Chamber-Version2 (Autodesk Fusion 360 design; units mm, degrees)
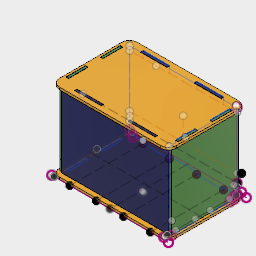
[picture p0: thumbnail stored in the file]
parameter "height" = 30
parameter "gap" = 0.2
parameter "tabWidth" = 30
parameter "tabGap" = 0.1
parameter "thickness" = 3
parameter "offset" = 4
parameter "width" = 150
parameter "length" = 100
parameter "fillet" = 10
sketch "Sketch2" plane through (0, 0, 0) normal (0, 1, 0) x axis (1, 0, 0)
  line L1 (150, 0) -> (0, 0)
  line L2 (150, 100) -> (150, 0)
  line L3 (0, 100) -> (150, 100)
  line L4 (0, 0) -> (0, 100)
  point P2 (0, 0)
  point P3 (150, 0)
  point P5 (0, 100)
  dimension "d10" distance P2 P3 = 150 (= "width")
  dimension "d11" distance P2 P5 = 100 (= "length")
extrude "Extrude1" new body sketch "Sketch2" along normal blind 3 (= "thickness") bodies "Bottom"
fillet "Fillet1" radius 10 (= "fillet")
work_plane "WorkPlane1" sketch "Sketch2" AlongDistance 30 (= "height")
fillet "Fillet2" radius 10 (= "fillet")
fillet "Fillet3" radius 10 (= "fillet")
fillet "Fillet4" radius 10 (= "fillet")
sketch "BOTTOM PartA" plane through (40, 30, -60) normal (0, 1, 0) x axis (1, 0, 0)
  line L1 (-30, 40) -> (100, 40)
  line L2 (-40, -50) -> (-40, 30)
  line L3 (100, -60) -> (-30, -60)
  line L4 (110, 30) -> (110, -50)
  arc A1 centre (100, 30) radius 10 clockwise from (100, 40) to (110, 30)
  arc A2 centre (-30, 30) radius 10 clockwise from (-40, 30) to (-30, 40)
  arc A3 centre (-30, -50) radius 10 clockwise from (-30, -60) to (-40, -50)
  arc A4 centre (100, -50) radius 10 clockwise from (110, -50) to (100, -60)
work_plane "WorkPlane2" AlongDistance -6 (= "-thickness * 2")
sketch "RIGHT" plane through (144, 1, -60) normal (1, 0, 0) x axis (0, 0, -1)
  line L1 (-50, 2.2) -> (30, 2.2)
  line L2 (-50, 2) -> (-50, -1)
  line L3 (30, -1) -> (30, 2)
  line L4 (-50, 2) -> (-60, 2)
  line L5 (-55.3241, 2.2) -> (-55.3241, 2)
  line L6 (-58.1845, 2.2) -> (-55.3241, 2.2)
  line L7 (-19.685, 102.4) -> (-44.685, 102.4)
  line L8 (-19.685, 99.2) -> (-19.685, 102.4)
  line L9 (-44.685, 102.4) -> (-44.685, 99.2)
  line L10 (-32.185, 102.4) -> (-32.185, 99.2)
  line L11 (24.7595, 102.4) -> (24.7595, 99.2)
  line L12 (-0.2405, 102.4) -> (24.7595, 102.4)
  line L13 (-0.2405, 99.2) -> (-0.2405, 102.4)
  line L14 (-44.7222, -1) -> (-44.7222, 2.2)
  line L15 (-19.7222, -1) -> (-44.7222, -1)
  line L16 (-19.7222, 2.2) -> (-19.7222, -1)
  line L17 (-0.2778, 2.2) -> (-0.2778, -1)
  line L18 (-0.2778, -1) -> (24.7222, -1)
  line L19 (24.7222, -1) -> (24.7222, 2.2)
  line L20 (-53, 15.5) -> (-50, 15.5)
  line L21 (33.0372, 15.5) -> (30.0372, 15.5)
  line L22 (-50, 2.2) -> (-55.3241, 2.2)
  line L23 (-53, 2.2) -> (-53, 15.5)
  line L24 (-53, 2.2) -> (-50, 2.2)
  line L25 (-53.036, 99.2) -> (-53, 15.5)
  line L26 (-53.036, 99.2) -> (-49.9628, 99.2)
  line L27 (33.0372, 101.1482) -> (33.0372, 15.5)
  line L28 (40, 2) -> (30, 2)
  line L29 (33.0372, 2) -> (33.0372, 101.1482)
  line L30 (33.0372, 2.2) -> (30, 2.2)
  line L31 (33.0372, 99.2027) -> (30.0372, 99.2)
  line L32 (33.0372, 2.2) -> (33.0372, 99.2027)
  line L33 (33.0372, 102) -> (33.0372, 2)
  line L34 (-53, 99.2) -> (-53, 2.2)
  line L35 (-44.685, 99.2) -> (-49.9628, 99.2)
  line L36 (-0.2405, 99.2) -> (-19.685, 99.2)
  line L37 (30.0372, 99.2) -> (24.7595, 99.2)
  point P11 (-55.3241, 2)
  point P12 (-55.3241, 2.2)
  point P16 (-44.685, 102.4)
  point P17 (-19.685, 102.4)
  point P19 (-44.685, 99.2)
  point P14 (-50, 15.5)
  point P34 (-53, 15.5)
  point P15 (30.0372, 15.5)
  point P35 (33.0372, 15.5)
  point P41 (33.0372, 2)
  point P44 (33.0372, 102)
  point P36 (-53, 2.2)
  point P45 (-53, 99.2)
  dimension "d28" distance P11 P12 = 0.2 (= "gap")
  dimension "d31" distance P16 P17 = 25 (= "length / 4")
  dimension "d32" distance P16 P19 = 3.2 (= "thickness + gap")
  dimension "d89" distance P14 P34 = 3 (= "thickness")
  dimension "d90" distance P15 P35 = 3 (= "thickness")
  dimension "d101" distance P41 P44 = 100
  dimension "d102" distance P36 P45 = 97 (= "100 mm - thickness")
extrude "Extrude3" new body sketch "RIGHT" profile of L1 L7 L8 L9 L11 L12 L13 L14 L15 L16 L17 L18 L19 along normal blind 3 (= "thickness") bodies "Right"
work_plane "WorkPlane3"
work_plane "WorkPlane4" AlongDistance -6 (= "-thickness * 2")
sketch "BACK" plane through (40, 1, -94) normal (0, 0, -1) x axis (1, 0, 0)
  line L1 (-30, 1) -> (-30, -2)
  line L2 (110, -28.8) -> (110, -29)
  line L3 (104, -15.5) -> (-94.0061, -15.5)
  line L4 (104, -26.3027) -> (-34, -26.3027)
  line L5 (35, -55.5802) -> (35, -26.3027)
  line L6 (-33.7633, -93.8824) -> (0.2632, -93.8824)
  line L7 (-16.7501, -99.1805) -> (-16.7501, -93.8824)
  line L8 (-16.7501, -102.3805) -> (-16.7501, -99.1805)
  line L9 (35, -93.8824) -> (-0.5953, -93.8824)
  line L10 (17.2024, -99.1805) -> (17.2024, -93.8824)
  line L11 (17.2024, -102.3805) -> (17.2024, -99.1805)
  line L12 (17.2024, -102.3805) -> (-16.7501, -102.3805)
  line L13 (-16.7501, 1) -> (-16.7501, -2.2)
  line L14 (17.2024, 1) -> (17.2024, -2.2)
  line L15 (17.2024, 1) -> (-16.7501, 1)
  line L16 (69.5, -93.8747) -> (35, -93.8824)
  line L17 (104, -93.8747) -> (69.5, -93.8747)
  line L18 (52.25, -99.1805) -> (52.25, -93.8786)
  line L19 (86.75, -99.1805) -> (86.75, -93.8747)
  line L20 (52.25, 1) -> (52.25, -2.2)
  line L21 (86.75, 1) -> (86.75, -2.2)
  line L22 (86.75, 1) -> (52.25, 1)
  line L23 (52.25, -102.3805) -> (52.25, -99.1805)
  line L24 (86.75, -102.3805) -> (86.75, -99.1805)
  line L25 (86.75, -102.3805) -> (52.25, -102.3805)
  line L26 (17.2024, -99.1805) -> (52.25, -99.1805)
  line L27 (52.25, -2.2) -> (17.2024, -2.2)
  line L28 (103.8, -2.2) -> (103.8, -10.9343)
  line L29 (103.8, -93.8747) -> (103.8, -10.9343)
  line L30 (103.8, -99.1805) -> (86.75, -99.1805)
  line L31 (103.8, -93.8747) -> (103.8, -99.1805)
  line L32 (103.8, -2.2) -> (86.75, -2.2)
  line L33 (104, -2.2) -> (104, -99.2027)
  line L34 (104, -2.2) -> (104, -15.5)
  line L35 (103.9, -10.9313) -> (104, -10.9313)
  line L36 (-33.7001, -20.8392) -> (-33.6001, -20.8392)
  line L37 (-33.7001, -99.1805) -> (-33.7001, -20.8392)
  line L38 (-33.7001, -99.1805) -> (-16.7501, -99.1805)
  line L39 (-33.7001, -15.5) -> (-33.7001, -20.8392)
  line L40 (-33.7001, -2.1805) -> (-33.7001, -15.5)
  line L41 (-33.7001, -99.1805) -> (-33.7001, -2.1805)
  line L42 (-16.75, -2.1805) -> (-33.7001, -2.1805)
  point P17 (-16.7501, -99.1805)
  point P18 (-16.7501, -102.3805)
  point P22 (17.2024, -99.1805)
  point P23 (17.2024, -102.3805)
  point P24 (-16.7501, -2.2)
  point P25 (-16.7501, 1)
  point P26 (17.2024, -2.2)
  point P27 (17.2024, 1)
  point P34 (52.25, -2.2)
  point P35 (52.25, 1)
  point P36 (86.75, -2.2)
  point P37 (86.75, 1)
  point P31 (52.25, -99.1805)
  point P38 (52.25, -102.3805)
  point P33 (86.75, -99.1805)
  point P39 (86.75, -102.3805)
  point P49 (104, -10.9313)
  point P50 (103.9, -10.9313)
  point P51 (-33.6001, -20.8392)
  point P52 (-33.7001, -20.8392)
  point P55 (-33.7001, -2.1805)
  point P56 (-33.7001, -99.1805)
  dimension "d53" distance P17 P18 = 3.2 (= "thickness + gap")
  dimension "d54" distance P22 P23 = 3.2 (= "thickness + gap")
  dimension "d55" distance P24 P25 = 3.2 (= "thickness + gap")
  dimension "d56" distance P26 P27 = 3.2 (= "thickness + gap")
  dimension "d57" distance P34 P35 = 3.2 (= "thickness + gap")
  dimension "d58" distance P36 P37 = 3.2 (= "thickness + gap")
  dimension "d59" distance P31 P38 = 3.2 (= "thickness + gap")
  dimension "d60" distance P33 P39 = 3.2 (= "thickness + gap")
  dimension "d97" distance P49 P50 = 0.1
  dimension "d98" distance P51 P52 = 0.1
  dimension "d103" distance P55 P56 = 97 (= "100 mm - thickness")
work_plane "WorkPlane5"
sketch "BOTTOM PartB" plane through (0, 0, 0) normal (0, -1, 0) x axis (1, 0, 0)
  line L1 (150, -10) -> (150, -90)
  line L2 (10, 0) -> (140, 0)
  line L3 (0, -90) -> (0, -10)
  line L4 (140, -100) -> (10, -100)
  line L5 (150, -50) -> (0, -50)
  line L6 (75, 0) -> (75, -100)
  line L7 (76, -40.2778) -> (78, -40.2778)
  line L8 (23.2499, 0) -> (23.2499, -94)
  line L9 (57.2024, 0) -> (57.2024, -94)
  line L10 (92.25, 0) -> (92.25, -94)
  line L11 (126.75, 0) -> (126.75, -94)
  line L12 (143.85, -84.7722) -> (146.95, -84.7722)
  line L13 (143.85, -59.6722) -> (143.85, -84.7722)
  line L14 (146.95, -59.6722) -> (143.85, -59.6722)
  line L15 (146.95, -84.7722) -> (146.95, -59.6722)
  line L16 (147.05, -15.2278) -> (143.95, -15.2278)
  line L17 (143.95, -15.2278) -> (143.95, -40.3278)
  line L18 (147.05, -40.3278) -> (147.05, -15.2278)
  line L19 (143.95, -40.3278) -> (147.05, -40.3278)
  line L20 (3.05, -57.8538) -> (0, -57.8538)
  line L21 (0, -100) -> (150, -100)
  line L22 (3.05, -100) -> (3.05, -57.8538)
  line L23 (150, 0) -> (0, 0)
  line L24 (3.05, 0) -> (3.05, -57.8538)
  line L25 (3.05, -59.6722) -> (3.05, -84.7722)
  line L26 (6.15, -84.7722) -> (6.15, -59.6722)
  line L27 (6.15, -59.6722) -> (3.05, -59.6722)
  line L28 (3.05, -84.7722) -> (6.15, -84.7722)
  line L29 (6.25, -40.3278) -> (6.25, -15.2278)
  line L30 (3.15, -15.2278) -> (3.15, -40.3278)
  line L31 (6.25, -15.2278) -> (3.15, -15.2278)
  line L32 (3.15, -40.3278) -> (6.25, -40.3278)
  arc A1 centre (140, -90) radius 10 clockwise from (150, -90) to (140, -100)
  arc A2 centre (140, -10) radius 10 clockwise from (140, 0) to (150, -10)
  arc A3 centre (10, -10) radius 10 clockwise from (0, -10) to (10, 0)
  arc A4 centre (10, -90) radius 10 clockwise from (10, -100) to (0, -90)
  point P34 (146.95, -84.7722)
  point P37 (146.95, -59.6722)
  point P35 (143.85, -84.7722)
  point P38 (147.05, -40.3278)
  point P41 (147.05, -15.2278)
  point P39 (143.95, -40.3278)
  point P50 (6.15, -84.7722)
  point P53 (6.15, -59.6722)
  point P51 (3.05, -84.7722)
  point P54 (6.25, -40.3278)
  point P57 (6.25, -15.2278)
  point P55 (3.15, -40.3278)
  dimension "d63" distance P34 P37 = 25.1 (= "25 mm + tabGap")
  dimension "d64" distance P34 P35 = 3.1 (= "thickness + tabGap")
  dimension "d65" distance P38 P41 = 25.1 (= "25 mm + tabGap")
  dimension "d66" distance P38 P39 = 3.1 (= "thickness + tabGap")
  dimension "d70" distance P50 P53 = 25.1 (= "25 mm + tabGap")
  dimension "d71" distance P50 P51 = 3.1 (= "thickness + tabGap")
  dimension "d72" distance P54 P57 = 25.1 (= "25 mm + tabGap")
  dimension "d73" distance P54 P55 = 3.1 (= "thickness + tabGap")
extrude "Extrude9" cut sketch "BOTTOM PartB" profile of L25 L26 L27 L28 L29 L30 L31 L32 against normal blind 6 (magnitude of "-thickness * 2")
extrude "Extrude8" cut sketch "BOTTOM PartB" profile of L12 L13 L14 L15 L16 L17 L18 L19 against normal blind 6 (magnitude of "-thickness * 2")
copy_paste_bodies "CopyPasteBodies1"
move "Move1"
move "Move2"
copy_paste_bodies "CopyPasteBodies2"
move "Move3"
sketch "BOTTOM PartC" plane through (0, 0, 0) normal (0, -1, 0) x axis (1, 0, 0)
  line L1 (23.2499, 0) -> (23.2499, -94)
  line L2 (23.2499, -91) -> (23.2499, -94)
  line L3 (23.1999, -93.0207) -> (23.2499, -93.0207)
  line L4 (57.2024, -94) -> (23.2499, -94)
  line L5 (23.4273, -94.05) -> (23.4273, -94)
  line L6 (57.2524, -91) -> (57.2024, -91)
  line L7 (23.2499, -91) -> (57.2024, -91)
  line L8 (57.1054, -90.95) -> (57.1054, -91)
  line L9 (23.1659, -94.05) -> (23.4273, -94.05)
  line L10 (57.4922, -94.05) -> (23.4273, -94.05)
  line L11 (57.2524, -94.05) -> (57.2524, -91)
  line L12 (23.2499, -90.95) -> (57.2024, -90.95)
  line L13 (23.1999, -90.95) -> (23.1999, -93.0207)
  line L14 (23.2499, -90.95) -> (23.1999, -90.95)
  line L15 (57.2524, -90.95) -> (23.1999, -90.95)
  line L16 (57.2524, -94.05) -> (57.2524, -90.95)
  line L17 (23.1999, -94.05) -> (57.2524, -94.05)
  line L18 (23.1999, -90.95) -> (23.1999, -94.05)
  line L19 (140, 0) -> (10, 0)
  line L20 (-10, -6) -> (34.9054, -6)
  line L21 (34.9054, -6) -> (-10, -6)
  line L22 (34.9054, -6) -> (152.6418, -6)
  line L23 (92.2499, -90.95) -> (126.7885, -90.95)
  line L24 (92.1999, -94.05) -> (126.7885, -94.05)
  line L25 (92.1999, -90.95) -> (92.1999, -94.05)
  line L26 (126.7885, -90.95) -> (126.7885, -94.05)
  line L27 (92.1999, -90.95) -> (92.2499, -90.95)
  line L28 (57.2524, -6) -> (57.2024, -6)
  line L29 (126.7885, -5.95) -> (126.7885, -9.05)
  line L30 (92.1999, -5.95) -> (92.2499, -5.95)
  line L31 (92.2499, -5.95) -> (126.7885, -5.95)
  line L32 (57.2524, -9.05) -> (57.2524, -5.95)
  line L33 (23.2499, -5.95) -> (23.1999, -5.95)
  line L34 (23.2499, -6) -> (23.2499, -9)
  line L35 (57.2524, -9.05) -> (57.2524, -6)
  line L36 (23.2499, -5.95) -> (57.2024, -5.95)
  line L37 (23.2499, -6) -> (57.2024, -6)
  line L38 (23.1999, -5.95) -> (23.1999, -9.05)
  line L39 (23.1999, -9.05) -> (57.2524, -9.05)
  line L40 (57.2524, -5.95) -> (23.1999, -5.95)
  line L41 (23.1999, -5.95) -> (23.1999, -8.0207)
  line L42 (57.4922, -9.05) -> (23.4273, -9.05)
  line L43 (23.1659, -9.05) -> (23.4273, -9.05)
  line L44 (23.4273, -9.05) -> (23.4273, -9)
  line L45 (57.2024, -9) -> (23.2499, -9)
  line L46 (23.1999, -8.0207) -> (23.2499, -8.0207)
  line L47 (92.1999, -5.95) -> (92.1999, -9.05)
  line L48 (57.1054, -5.95) -> (57.1054, -6)
  line L49 (92.1999, -9.05) -> (126.7885, -9.05)
  point P6 (23.2499, -93.0207)
  point P7 (23.1999, -93.0207)
  point P9 (23.4273, -94)
  point P10 (23.4273, -94.05)
  point P12 (57.2024, -91)
  point P13 (57.2524, -91)
  point P15 (57.1054, -91)
  point P16 (57.1054, -90.95)
  point P50 (23.2499, -8.0207)
  point P51 (23.1999, -8.0207)
  point P42 (23.4273, -9)
  point P49 (23.4273, -9.05)
  point P36 (57.2524, -6)
  point P48 (57.2024, -6)
  point P39 (57.1054, -6)
  point P40 (57.1054, -5.95)
  dimension "d76" distance P6 P7 = 0.05
  dimension "d77" distance P9 P10 = 0.05
  dimension "d78" distance P12 P13 = 0.05
  dimension "d79" distance P15 P16 = 0.05
  dimension "d81" distance P50 P51 = 0.05
  dimension "d82" distance P42 P49 = 0.05
  dimension "d83" distance P36 P48 = 0.05
  dimension "d84" distance P39 P40 = 0.05
extrude "Extrude10" cut sketch "BOTTOM PartC" profile of L9 L10 L11 L15 L16 L18 L21 L23 L24 L25 L26 L27 L28 L29 L30 L31 L32 L35 L37 L38 L42 L43 L47 L49 against normal blind 6 (magnitude of "-thickness * 2")
extrude "Extrude11" cut sketch "BOTTOM PartC" profile of L9 L10 L11 L15 L16 L18 L21 L23 L24 L25 L26 L27 L28 L29 L30 L31 L32 L35 L37 L38 L42 L43 L47 L49 against normal blind 50
extrude "Extrude12" new body sketch "BACK" profile of L8 L11 L12 L13 L14 L15 L20 L21 L22 L23 L24 L25 L26 L27 L28 L29 L30 L31 L32 no distance stored bodies "Back"
copy_paste_bodies "CopyPasteBodies5"
move "Move7"
move "Move8"
move "Move9"
move "Move10"
move "Move11"
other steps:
base_feature "Base Feature1" bodies "Right", "Left"
base_feature "Base Feature2" bodies "Bottom", "Top"
base_feature "Base Feature5" bodies "Back", "Front"
named bodies: "Bottom", "Right", "Left", "Top", "Back", "Front"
